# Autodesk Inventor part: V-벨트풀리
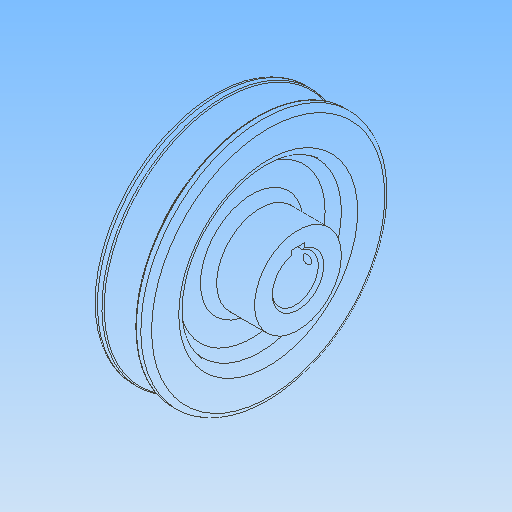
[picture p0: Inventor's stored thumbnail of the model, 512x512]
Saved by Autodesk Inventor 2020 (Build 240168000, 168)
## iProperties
Created: 2015-09
Part Number: V-벨트풀리
Material: 강철, 연강
Document SubType Name: Modeling
Designer: mduedu
Density: 7.86 g/cm^3
Mass: 779.014 g
Surface Area: 277.465 cm^2
Volume: 99.1112 cm^3
Appearance: 강철
Author: mduedu
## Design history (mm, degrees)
sketch "스케치1"
  geometry: L1 (-10, 0)-(10, 0); L2 (-10, 0)-(-10, 45); L3 (-10, 45)-(-5.976, 45); L4 (-5.976, 45)-(-2.154, 32.5); L5 (-2.154, 32.5)-(2.154, 32.5); L6 (2.154, 32.5)-(5.976, 45); L7 (5.976, 45)-(10, 45); L8 (10, 45)-(10, 0); L9 (0, 0)-(0, 32.5); L10 (-10, 40.5)-(10, 40.5); 3 further points
  constraints: 20 end point, 6 point on line, 3 perpendicular, 2 midpoint, 2 parallel, 2 symmetric about line, 1 coincident, 1 collinear, 1 equal length, 1 horizontal, 1 vertical, 1 vertical alignment
  dimensions: "d0" = 20 distance between parallel lines of L8 L2; "d2" = 90 diameter of L3 L1; "d5" = 8 distance between parallel lines of L5 L10; "d6" = 9.2 distance of point (4.6, 40.5) point (-4.6, 40.5); "d7" = 34 deg angle of L6 L4; "d40" = 4.5 distance between parallel lines of L3 L10
revolve "회전1" sketch "스케치1" stored, may be unused: angle "d8" = 90 deg
sketch "스케치2"
  geometry: C1 r 16 at (0, 0); 1 further point
  constraints: 1 centre point, 1 coincident
  dimensions: "d9" = 32 diameter of C1
extrude "돌출1" join sketch "스케치2" distance "d10" = 11; taper "d11" = 0 deg
fillet "모깎기1" dims "d12" = 1, "d13" = 0.5, "d14" = 2
sketch "스케치3"
  geometry: C1 r 16 at (0, 0) reference; C2 r 30 at (0, 0); 1 further point
  constraints: 1 centre point, 1 coincident
  dimensions: "d15" = 60 diameter of C2
extrude "돌출2" cut sketch "스케치3" distance "d16" = 6; taper "d17" = 0 deg
fillet "모깎기2" dims "d18" = 3
fillet "모깎기3" dims "d19" = 3
fillet "모깎기4" dims "d20" = 3
sketch "스케치4"
  geometry: C1 r 8.5 at (0, 0); 1 further point
  constraints: 1 centre point, 1 coincident
  dimensions: "d21" = 17 diameter of C1
extrude "돌출3" cut sketch "스케치4" extent not by distance; stored distance "d22" = 4; taper "d23" = 0 deg
sketch "스케치5"
  geometry: L1 (-2.5, 8.124)-(2.5, 8.124); L2 (2.5, 8.124)-(2.5, 10.8); L3 (2.5, 10.8)-(-2.5, 10.8); L4 (-2.5, 10.8)-(-2.5, 8.124); A1 r 8.5 centre (0, 0) between (-2.5, 8.124) and (2.5, 8.124) reference; 2 further points
  constraints: 8 end point, 3 point on circle, 2 parallel, 1 horizontal, 1 perpendicular, 1 vertical alignment
  dimensions: "d24" = 5 distance of L2.end L3.end; "d26" = 19.3 distance from line of L3 point (0, -8.5)
extrude "돌출4" cut sketch "스케치5" extent not by distance; stored distance "d27" = 4; taper "d28" = 0 deg
chamfer "모따기1" distance "d29" = 1; stored, may be unused: second distance "d30" = 2, angle "d31" = 45 deg
node "작업 평면1"
sketch "스케치6"
  geometry: L1 (-11, 16)-(-11, -16) reference; 2 further points
  constraints: 1 horizontal alignment
  dimensions: "d32" = 5 distance from line of point (-6, 0) L1
hole "구멍1" sketch "스케치6" at (-6, 0) diameter "d33" = 3.242; stored, may be unused: countersink angle "d37" = 90 deg, drill point angle "d39" = 118 deg; dims "d34" = 6, "d35" = 4, "d36" = 2, "d38" = 8
node "솔리드1"
mirror "대칭1"
